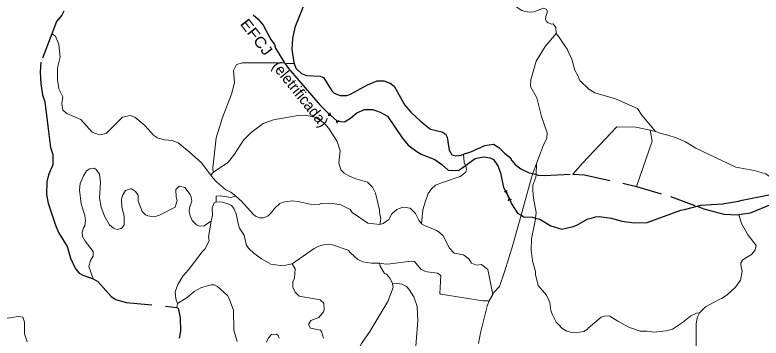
# Model space of a CAD drawing. Extents: x 423 to 448.8, y 7456.3 to 7484.
# Drawn here: x 438.44 to 443.98, y 7467.89 to 7470.29 of the extents above; entities that cross this region are included whole.
import ezdxf
from ezdxf.enums import TextEntityAlignment as Align

# ---------------------------------------------------------------- set-up
doc = ezdxf.new("R2010")
doc.units = 0
doc.header["$LTSCALE"] = 0.032
doc.linetypes.add('LONG_DASHED', pattern=[7.5, 6, -1.5])
doc.linetypes.add('MEDIUM_DASHED', pattern=[4.5, 3, -1.5])
for name, color, linetype, lineweight in [('15', 7, 'Continuous', 25), ('31', 7, 'Continuous', 25), ('4', 7, 'LONG_DASHED', 25), ('5', 7, 'LONG_DASHED', 13), ('6', 7, 'MEDIUM_DASHED', 13), ('7', 7, 'Continuous', 13)]:
    doc.layers.add(name, color=color, linetype=linetype, lineweight=lineweight)
doc.layers.add('61', color=7, linetype='Continuous')

msp = doc.modelspace()

# ---------------------------------------------------------------- linework, layer by layer
at = {"layer": '15'}
for points in [[(440.2123, 7470.2868), (440.2492, 7470.2546), (440.2862, 7470.2112), (440.3435, 7470.1032), (440.3699, 7470.0661), (440.3764, 7470.0404), (440.4403, 7469.9378), (440.4473, 7469.9278)], [(440.4473, 7469.9278), (440.4746, 7469.8887), (440.7072, 7469.6184), (440.7688, 7469.5575), (440.7849, 7469.5432), (440.8333, 7469.5001), (440.8355, 7469.4979), (440.8884, 7469.494), (440.9333, 7469.5213), (440.9811, 7469.5592), (441.0386, 7469.5852), (441.1002, 7469.5855), (441.1554, 7469.5663), (441.2086, 7469.5353), (441.3168, 7469.3756), (441.3621, 7469.3215), (441.4328, 7469.2691), (441.4594, 7469.2545), (441.5608, 7469.2141), (441.6123, 7469.1772), (441.6586, 7469.1351), (441.7349, 7469.1313), (441.7882, 7469.17), (441.8592, 7469.2214), (441.9221, 7469.2331), (441.9696, 7469.2262), (441.9953, 7469.215), (442.028, 7469.1661), (442.0469, 7469.1162), (442.0709, 7469.0054), (442.0904, 7468.9729), (442.0942, 7468.9643), (442.1131, 7468.9221), (442.1301, 7468.8844), (442.1731, 7468.8156), (442.2012, 7468.8003), (442.2214, 7468.7894), (442.2841, 7468.7855), (442.3073, 7468.7793), (442.3398, 7468.7705), (442.4199, 7468.7232), (442.5039, 7468.698), (442.5879, 7468.716), (442.6137, 7468.7263), (442.6948, 7468.7749), (442.7124, 7468.7761), (442.7528, 7468.7899), (442.7803, 7468.7924), (442.8704, 7468.7782), (442.9486, 7468.7572), (443.0427, 7468.745), (443.1359, 7468.7478), (443.3867, 7468.8379), (443.4244, 7468.8448), (443.5068, 7468.8675), (443.5328, 7468.8746), (443.6961, 7468.8863), (443.8131, 7468.904), (443.8418, 7468.9135), (444.0525, 7468.9551)]]:
    msp.add_lwpolyline(points, dxfattribs=at)
at = {"layer": '31'}
for p, q in [((440.7675, 7469.5422), (440.7849, 7469.5432)), ((440.7849, 7469.5432), (440.784, 7469.5606)), ((440.7849, 7469.5432), (440.8332, 7469.5002)), ((440.8332, 7469.5002), (440.8509, 7469.5013)), ((440.8344, 7469.4827), (440.8332, 7469.5002)), ((442.0764, 7468.9782), (442.0904, 7468.9729)), ((442.0904, 7468.9729), (442.0958, 7468.9869)), ((442.0904, 7468.9729), (442.113, 7468.9222)), ((442.1076, 7468.9083), (442.113, 7468.9222)), ((442.113, 7468.9222), (442.1269, 7468.9168))]:
    msp.add_line(p, q, dxfattribs=at)
at = {"layer": '4'}
for points in [[(440.5851, 7470.3547), (440.5207, 7470.1932), (440.5027, 7470.1125), (440.4975, 7470.0318), (440.5107, 7469.9488), (440.517, 7469.9273), (440.5279, 7469.8905), (440.537, 7469.8806), (440.5713, 7469.8514), (440.6074, 7469.8377), (440.7088, 7469.8333), (440.7346, 7469.8231), (440.7947, 7469.7234), (440.8118, 7469.7071), (440.8582, 7469.6899), (440.908, 7469.6882), (440.9338, 7469.6976), (441.0609, 7469.7681), (441.1313, 7469.7973), (441.1812, 7469.7982), (441.2292, 7469.781), (441.2576, 7469.7586), (441.3366, 7469.6161), (441.3821, 7469.5654), (441.4542, 7469.4975), (441.529, 7469.4392), (441.6123, 7469.4203), (441.6363, 7469.4039), (441.6397, 7469.4056), (441.6509, 7469.3808), (441.6668, 7469.2844), (441.6868, 7469.2486), (441.7166, 7469.2402), (441.7566, 7469.2467), (441.7739, 7469.2528), (441.8282, 7469.2719), (441.9318, 7469.318), (441.9962, 7469.3266), (442.0339, 7469.3028), (442.0795, 7469.258), (442.1095, 7469.2365), (442.1258, 7469.2167), (442.1258, 7469.2107), (442.1361, 7469.2038), (442.1379, 7469.1961), (442.1559, 7469.1772), (442.1989, 7469.1437), (442.2599, 7469.1162), (442.288, 7469.109), (442.3117, 7469.103), (442.3268, 7469.0991), (442.3732, 7469.0965), (442.5836, 7469.1057), (442.6704, 7469.1008), (443.0573, 7469.015), (443.3094, 7468.9393), (443.5068, 7468.8675), (443.557, 7468.8492), (443.7061, 7468.8096), (443.8041, 7468.8036), (443.8173, 7468.8056), (443.902, 7468.8182), (444.0582, 7468.8835)], [(438.8051, 7470.3134), (438.7902, 7470.2846), (438.7514, 7470.2387), (438.7163, 7470.1459), (438.6367, 7469.9359), (438.6312, 7469.8617), (438.6367, 7469.7748), (438.6481, 7469.6939), (438.6645, 7469.6418), (438.6862, 7469.4615), (438.7072, 7469.3029), (438.7236, 7469.2506), (438.7257, 7469.1987), (438.724, 7469.1746), (438.6922, 7469.1008), (438.6793, 7469.0493), (438.6765, 7468.9533), (438.6896, 7468.8912), (438.7437, 7468.7263), (438.7669, 7468.6714), (438.83, 7468.568), (438.8553, 7468.4829), (438.8932, 7468.4034), (438.919, 7468.3716), (438.9464, 7468.3561), (439.0237, 7468.3295), (439.0598, 7468.3089), (439.1568, 7468.199), (439.1929, 7468.1749), (439.2694, 7468.1543), (439.6455, 7468.1174), (439.655, 7468.1122), (439.6687, 7468.0393), (439.6734, 7467.9415), (439.6618, 7467.8881)]]:
    msp.add_lwpolyline(points, dxfattribs=at)
at = {"layer": '5'}
msp.add_lwpolyline([(441.8854, 7467.8503), (441.9, 7467.9293), (441.9472, 7468.12), (441.9627, 7468.1646), (441.9902, 7468.2121), (441.999, 7468.2272)], dxfattribs=at)
at = {"layer": '6'}
msp.add_lwpolyline([(438.3848, 7468.0375), (438.4706, 7468.0487), (438.5007, 7468.0444), (438.5153, 7468.0083), (438.5148, 7467.9218), (438.5339, 7467.8624)], dxfattribs=at)
at = {"layer": '7'}
for p, q in [((439.8979, 7469.0985), (439.9167, 7469.1213)), ((439.6455, 7468.1174), (439.6509, 7468.1447))]:
    msp.add_line(p, q, dxfattribs=at)
for points in [[(442.4611, 7470.1481), (442.4588, 7470.1935), (442.4391, 7470.2195), (442.4276, 7470.2188), (442.402, 7470.2288), (442.3903, 7470.2354), (442.382, 7470.2531), (442.3844, 7470.2741), (442.3963, 7470.3116), (442.3864, 7470.329), (442.3664, 7470.3374), (442.2959, 7470.3097), (442.2634, 7470.3071), (442.2291, 7470.3121), (442.2061, 7470.3197), (442.179, 7470.3355), (442.0906, 7470.4145), (442.0651, 7470.4281), (442.043, 7470.4417), (442.0216, 7470.452), (442.0046, 7470.4531)], [(439.8979, 7469.0985), (439.8276, 7469.1884), (439.7374, 7469.2708), (439.6541, 7469.3378), (439.6103, 7469.355), (439.5511, 7469.3601), (439.5004, 7469.3756), (439.472, 7469.3936), (439.4513, 7469.4175), (439.4066, 7469.4653), (439.3338, 7469.5283), (439.2988, 7469.5395), (439.2428, 7469.5269), (439.121, 7469.4079), (439.072, 7469.3981), (439.0174, 7469.4177), (438.9334, 7469.5115), (438.8284, 7469.5563), (438.7976, 7469.5801), (438.7906, 7469.6291), (438.7976, 7469.6781), (438.7696, 7469.7382), (438.7584, 7469.8068), (438.7584, 7469.8936), (438.778, 7469.972), (438.7695, 7470.0678), (438.7444, 7470.1291), (438.7163, 7470.1459)], [(442.315, 7469.1852), (442.3673, 7469.3217), (442.3908, 7469.3699), (442.3927, 7469.4124), (442.3521, 7469.5334), (442.3172, 7469.6726), (442.2695, 7469.7547), (442.2738, 7469.8047), (442.3115, 7469.9425), (442.3787, 7470.0523), (442.4611, 7470.1481)], [(442.4611, 7470.1481), (442.4813, 7470.1246), (442.5311, 7470.0496), (442.5437, 7470.0295), (442.5487, 7470.0144), (442.5758, 7469.9588), (442.5992, 7469.8761), (442.6222, 7469.8369), (442.6375, 7469.7993), (442.7034, 7469.735), (442.7473, 7469.7086), (442.902, 7469.6629), (443.0645, 7469.5934), (443.0962, 7469.5423), (443.1987, 7469.4221)], [(439.9167, 7469.1213), (439.9119, 7469.1382), (439.911, 7469.1517), (439.9375, 7469.3756), (439.9831, 7469.5268), (440.05, 7469.6981), (440.073, 7469.782), (440.0666, 7469.8748), (440.0887, 7469.9195), (440.1328, 7469.9303), (440.3939, 7469.9317), (440.4473, 7469.9278), (440.4618, 7469.9267), (440.517, 7469.9273)], [(441.1518, 7468.7322), (441.1596, 7468.7738), (441.1483, 7468.8214), (441.1485, 7468.8405), (441.1193, 7468.9634), (441.0978, 7469.0088), (441.0609, 7469.0467), (440.9733, 7469.0715), (440.9226, 7469.0922), (440.8865, 7469.1128), (440.8633, 7469.1386), (440.8479, 7469.1892), (440.8565, 7469.2785), (440.835, 7469.3481), (440.774, 7469.4443), (440.7457, 7469.4753), (440.7096, 7469.5053), (440.6728, 7469.5278), (440.5954, 7469.5435), (440.5449, 7469.5414), (440.3626, 7469.5079), (440.2853, 7469.4812), (440.196, 7469.4151), (440.1402, 7469.3567), (440.0732, 7469.2528), (440.038, 7469.2098), (440.0225, 7469.1926), (439.9167, 7469.1213)], [(442.5836, 7469.1057), (442.6559, 7469.1875), (442.9111, 7469.4554), (443.0523, 7469.4537), (443.1589, 7469.4307), (443.1987, 7469.4221)], [(443.1589, 7469.4307), (443.1739, 7469.3504), (443.0573, 7469.015)], [(443.1987, 7469.4221), (443.2413, 7469.4061), (443.2894, 7469.3945), (443.3516, 7469.3738), (443.4213, 7469.3446), (443.4974, 7469.2991), (443.7938, 7469.1583), (443.9294, 7469.1317), (444.018, 7469.107), (444.0513, 7469.0825), (444.0749, 7469.0397), (444.1039, 7468.97)], [(441.7739, 7469.2528), (441.7783, 7469.193), (441.7882, 7469.17), (441.7903, 7469.1652), (441.7949, 7469.1435), (441.7903, 7469.1195), (441.747, 7469.0874), (441.6176, 7469.0423), (441.564, 7469.0246), (441.5361, 7468.9966), (441.5112, 7468.9617), (441.4873, 7468.8986), (441.47, 7468.8399), (441.4609, 7468.7378)], [(441.999, 7468.2272), (442.039, 7468.2722), (442.0771, 7468.3796), (442.1422, 7468.5889), (442.2012, 7468.8003), (442.224, 7468.8819), (442.2742, 7469.0699), (442.288, 7469.109), (442.315, 7469.1852)], [(443.5238, 7468.0769), (443.5019, 7468.0737), (443.4603, 7468.0545), (443.398, 7468.0037), (443.3237, 7467.9559), (443.2737, 7467.942), (443.1845, 7467.9327), (443.1341, 7467.94), (443.0849, 7467.94), (443.0044, 7467.969), (442.919, 7468.0144), (442.8601, 7468.0518), (442.8278, 7468.0541), (442.7947, 7468.0441), (442.6989, 7467.9628), (442.6912, 7467.9527), (442.6656, 7467.9371), (442.6316, 7467.9331), (442.6099, 7467.9286), (442.5773, 7467.93), (442.5408, 7467.9416), (442.5031, 7467.964), (442.4819, 7467.9859), (442.4616, 7468.0084), (442.4338, 7468.0626), (442.4219, 7468.0944), (442.4127, 7468.1538), (442.3885, 7468.2081), (442.3281, 7468.2802), (442.3084, 7468.3608), (442.3069, 7468.3839), (442.2857, 7468.4621), (442.2753, 7468.5419), (442.278, 7468.6248), (442.3064, 7468.7708), (442.3073, 7468.7793), (442.3115, 7468.8197), (442.2917, 7468.9265), (442.2877, 7468.9851), (442.288, 7469.0228), (442.3109, 7469.0823), (442.3117, 7469.103), (442.315, 7469.1852)], [(439.0237, 7468.3295), (438.9914, 7468.4206), (439.0037, 7468.4637), (439.0246, 7468.497), (439.0229, 7468.5322), (438.9644, 7468.6086), (438.9456, 7468.6439), (438.9413, 7468.6756), (438.9525, 7468.7083), (438.9619, 7468.722), (438.9671, 7468.7581), (438.9628, 7468.7976), (438.9353, 7468.8861), (438.9224, 7468.99), (438.9284, 7469.0372), (438.9516, 7469.0939), (438.9756, 7469.1291), (438.9997, 7469.1454), (439.0306, 7469.1488), (439.0452, 7469.1411), (439.0718, 7469.105), (439.0778, 7469.0424), (439.0718, 7468.9298), (439.0821, 7468.8603), (439.107, 7468.7941), (439.144, 7468.7306), (439.1749, 7468.7057), (439.2032, 7468.6945), (439.2316, 7468.7022), (439.2402, 7468.7092), (439.2539, 7468.7306), (439.2539, 7468.7443), (439.253, 7468.7933), (439.2367, 7468.8603), (439.2333, 7468.923), (439.2436, 7468.9513), (439.265, 7468.9831), (439.3003, 7468.9977), (439.3097, 7468.9969), (439.3389, 7468.9779), (439.3578, 7468.9487), (439.357, 7468.9058), (439.387, 7468.8285), (439.4119, 7468.8045), (439.4291, 7468.7967), (439.4738, 7468.7898), (439.5124, 7468.7993), (439.6318, 7468.8594), (439.6472, 7468.9101), (439.6404, 7468.9342), (439.6387, 7468.9917), (439.6618, 7469.0166), (439.7048, 7469.0054), (439.7443, 7468.9539), (439.752, 7468.9359), (439.7555, 7468.9058), (439.7391, 7468.8552), (439.7366, 7468.8302), (439.7434, 7468.7968), (439.7597, 7468.7615), (439.7898, 7468.7306), (439.8104, 7468.7203), (439.8482, 7468.7211), (439.8808, 7468.7435), (439.9004, 7468.756)], [(440.0829, 7468.9409), (440.0466, 7468.972), (440.0097, 7468.9891), (439.9392, 7469.0475), (439.913, 7469.0792), (439.8979, 7469.0985)], [(439.9376, 7468.9007), (439.9362, 7468.9421), (439.9709, 7468.9451), (440.0453, 7468.9332), (440.0829, 7468.9409)], [(441.1518, 7468.7322), (441.0628, 7468.7409), (440.9475, 7468.8208), (440.9321, 7468.8422), (440.8625, 7468.8775), (440.7869, 7468.8895), (440.7225, 7468.8878), (440.7079, 7468.886), (440.7053, 7468.8809), (440.6323, 7468.8837), (440.5447, 7468.9033), (440.4992, 7468.9067), (440.434, 7468.8972), (440.4107, 7468.8869), (440.3721, 7468.8543), (440.3464, 7468.8182), (440.3231, 7468.7967), (440.2871, 7468.7821), (440.2579, 7468.7821), (440.2296, 7468.7933), (440.2115, 7468.8079), (440.1247, 7468.905), (440.0829, 7468.9409)], [(439.9004, 7468.756), (439.9092, 7468.7996), (439.9073, 7468.8546), (439.922, 7468.8929), (439.9376, 7468.9007)], [(439.9376, 7468.9007), (439.9837, 7468.8968), (440.0234, 7468.8861), (440.0509, 7468.8731), (440.0689, 7468.8517), (440.0853, 7468.8113), (440.0998, 7468.7375), (440.111, 7468.7048), (440.1436, 7468.6525), (440.1617, 7468.5769), (440.1789, 7468.5537), (440.2175, 7468.5202), (440.2733, 7468.4772), (440.3429, 7468.4386), (440.4327, 7468.4252), (440.5013, 7468.4399)], [(441.9902, 7468.2121), (441.9541, 7468.3977), (441.9059, 7468.4344), (441.8702, 7468.4313), (441.8325, 7468.4459), (441.8136, 7468.4784), (441.7727, 7468.5078), (441.7025, 7468.5183), (441.6679, 7468.556), (441.6228, 7468.6472), (441.5932, 7468.6742), (441.5728, 7468.6867), (441.539, 7468.7027), (441.4834, 7468.7238), (441.4609, 7468.7378), (441.4402, 7468.7631), (441.4168, 7468.8128), (441.3776, 7468.8527), (441.323, 7468.8602), (441.2778, 7468.8432), (441.2409, 7468.8106), (441.2192, 7468.7692), (441.1757, 7468.7388), (441.1518, 7468.7322)], [(443.5238, 7468.0769), (443.5688, 7468.1208), (443.6708, 7468.1749), (443.6867, 7468.1839), (443.73, 7468.2112), (443.792, 7468.2675), (443.8278, 7468.319), (443.8406, 7468.3834), (443.8307, 7468.432), (443.8315, 7468.4467), (443.836, 7468.4558), (443.8447, 7468.4676), (443.8617, 7468.4807), (443.911, 7468.5087), (443.9263, 7468.5256), (443.9387, 7468.5444), (443.9464, 7468.5773), (443.8862, 7468.6538), (443.8365, 7468.7381), (443.8173, 7468.8056)], [(439.6509, 7468.1447), (439.6386, 7468.1801), (439.6326, 7468.2325), (439.6524, 7468.2857), (439.6893, 7468.3493), (439.7322, 7468.3956), (439.8328, 7468.5296), (439.8559, 7468.5519), (439.8843, 7468.6138), (439.8808, 7468.6406), (439.9004, 7468.756)], [(440.5013, 7468.4399), (440.6632, 7468.5546), (440.6985, 7468.5709), (440.7457, 7468.5838), (440.7998, 7468.582), (440.9166, 7468.5416), (440.9355, 7468.5184), (440.9873, 7468.4727), (441.0246, 7468.4551), (441.0892, 7468.4443), (441.15, 7468.4443)], [(441.15, 7468.4443), (441.1983, 7468.4378), (441.2292, 7468.4403), (441.3838, 7468.4592), (441.4079, 7468.4566), (441.4554, 7468.401), (441.4867, 7468.3853), (441.5037, 7468.3809), (441.5787, 7468.3709), (441.6054, 7468.3535), (441.5968, 7468.2204), (441.6037, 7468.2153), (441.9163, 7468.1646), (441.9627, 7468.1646)], [(440.7344, 7467.8889), (440.7199, 7467.9379), (440.7122, 7467.9473), (440.6375, 7467.9637), (440.6229, 7467.9894), (440.6391, 7468.0207), (440.7002, 7468.0418), (440.7345, 7468.0839), (440.7397, 7468.0994), (440.7354, 7468.1475), (440.7079, 7468.1741), (440.5542, 7468.2003), (440.5223, 7468.229), (440.5068, 7468.2673), (440.5061, 7468.3055), (440.5172, 7468.3347), (440.5241, 7468.4025), (440.5013, 7468.4399)], [(441.15, 7468.4443), (441.1545, 7468.424), (441.1871, 7468.3691), (441.2009, 7468.3639), (441.2259, 7468.334), (441.2465, 7468.2957), (441.247, 7468.291)], [(441.2472, 7467.4361), (441.3376, 7467.5434), (441.3881, 7467.6401), (441.4092, 7467.7034), (441.4342, 7468.0191), (441.4285, 7468.1242), (441.4045, 7468.1947), (441.3701, 7468.2496), (441.3486, 7468.2711), (441.3142, 7468.2891), (441.267, 7468.2969), (441.247, 7468.291)], [(439.6509, 7468.1447), (439.7218, 7468.1893), (439.7735, 7468.2353), (439.8293, 7468.2634), (439.8998, 7468.2848), (439.9229, 7468.2832), (439.9479, 7468.2728), (440.0227, 7468.2032), (440.0393, 7468.1689), (440.0653, 7468.0957), (440.067, 7467.9476), (440.0921, 7467.8632)], [(441.247, 7468.291), (441.2499, 7468.2634), (441.212, 7468.1612), (441.0764, 7467.9387), (441.0145, 7467.8486), (440.9819, 7467.785), (440.9802, 7467.7395), (440.9922, 7467.6906), (440.9887, 7467.6278), (441.0059, 7467.6038), (441.0661, 7467.584), (441.085, 7467.5729), (441.1107, 7467.5248), (441.135, 7467.5004), (441.2472, 7467.4361)], [(443.5336, 7467.2692), (443.4878, 7467.3404), (443.4865, 7467.3703), (443.4928, 7467.3814), (443.5512, 7467.4011), (443.5612, 7467.4087), (443.5655, 7467.4148), (443.5656, 7467.4207), (443.5633, 7467.4268), (443.4502, 7467.5587), (443.4726, 7467.6323), (443.4792, 7467.6748), (443.5011, 7467.8153), (443.5002, 7467.9973), (443.5099, 7468.0466), (443.5238, 7468.0769)], [(440.3111, 7467.8597), (440.3257, 7467.8924), (440.3489, 7467.9164), (440.385, 7467.9182), (440.3962, 7467.9087), (440.4047, 7467.8881)]]:
    msp.add_lwpolyline(points, dxfattribs=at)

# ---------------------------------------------------------------- texts
at = {"layer": '61', "width": 1.15}
msp.add_text('EFCJ', height=0.08, rotation=307.646, dxfattribs=at).set_placement((440.2044, 7470.0976), align=Align.CENTER)
at = {"layer": '61'}
msp.add_text('(eletrificada)', height=0.08, rotation=308.749, dxfattribs=at).set_placement((440.5306, 7469.675), align=Align.CENTER)

doc.saveas('drawing.dxf')
